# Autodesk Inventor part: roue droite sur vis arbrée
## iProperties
Created: 2011-07
Part Number: roue droite sur vis arbrée
Document SubType Name: Modeling
Designer: Laur
Density: 8.47 g/cm^3
Material: Laiton (jaune doux)
Mass: 0.78259 g
Surface Area: 1.71595 cm^2
Volume: 0.0923955 cm^3
Author: Laur
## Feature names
1. Révolution1 [Revolution]
